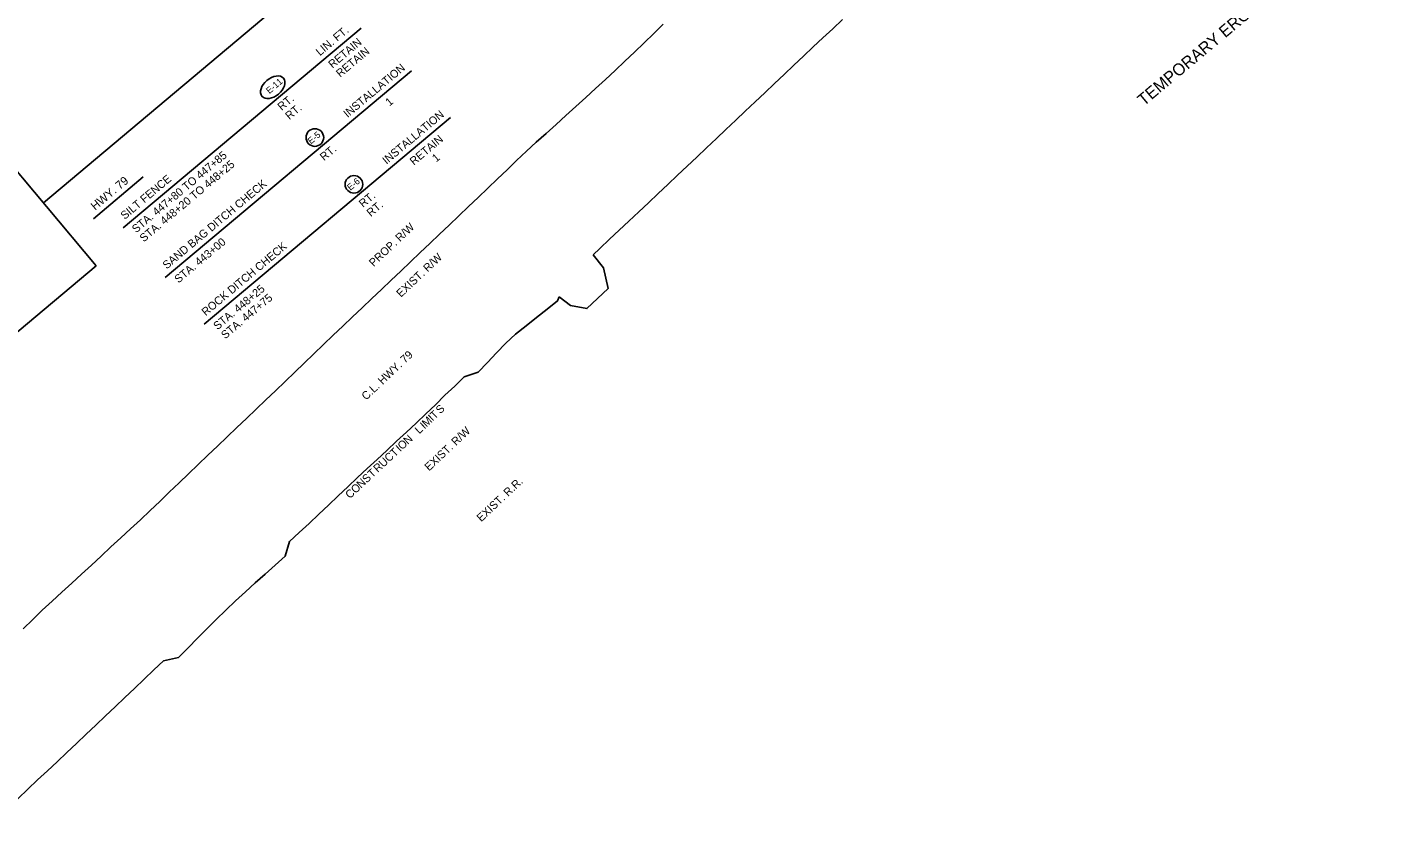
# Model space of a CAD drawing. Extents: x 1430270 to 1431940, y 1964631 to 1966264.
# Drawn here: x 1430913 to 1431940, y 1964816 to 1965408 of the extents above; entities that cross this region are included whole.
import ezdxf

# ---------------------------------------------------------------- set-up
doc = ezdxf.new("R2010")
doc.units = 0
for name, color, linetype in [('1', 7, 'Continuous'), ('44', 7, 'Continuous'), ('60', 7, 'Continuous'), ('R_Draft', 7, 'Continuous'), ('R_NO PLOT', 7, 'Continuous')]:
    doc.layers.add(name, color=color, linetype=linetype)

msp = doc.modelspace()

# ---------------------------------------------------------------- linework, layer by layer
at = {"layer": '1'}
for p, q in [((1430924.6, 1965276.1), (1431143.8, 1965460.1)), ((1430964.3, 1965228.8), (1430886.4, 1965321.6))]:
    msp.add_line(p, q, dxfattribs=at)
msp.add_lwpolyline([(1430680, 1965034.6), (1430701.8, 1965008.6), (1430964.3, 1965228.8)], dxfattribs=at)
for centre in [(1431128.1, 1965325), (1431157.4, 1965289.9)]:
    msp.add_circle(centre, 6.61, dxfattribs=at)
msp.add_ellipse((1431096.5, 1965362.7), major_axis=(8.06, 6.76), ratio=0.638788, dxfattribs=at)
at = {"layer": '44'}
for p, q in [((1430984.4, 1965257.3), (1431162.7, 1965406.9)), ((1431015.8, 1965220), (1431200.4, 1965374.9)), ((1431045.1, 1965185), (1431229.7, 1965339.9)), ((1430962.1, 1965264.1), (1430999.5, 1965295.5))]:
    msp.add_line(p, q, dxfattribs=at)
at = {"layer": 'R_NO PLOT'}
for points in [[(1430909.4, 1964956.7), (1430916.6, 1964963.7), (1430923.8, 1964970.6), (1430931.2, 1964977.4), (1430938.5, 1964984.2), (1430945.9, 1964990.9), (1430953.2, 1964997.7), (1430960.6, 1965004.4), (1430968, 1965011.2), (1430975.3, 1965018.1), (1430982.6, 1965024.8), (1430990, 1965031.6), (1430997.3, 1965038.4), (1431004.6, 1965045.3), (1431011.8, 1965052.2), (1431019, 1965059.1), (1431026.3, 1965066), (1431033.5, 1965072.9), (1431040.7, 1965079.8), (1431047.9, 1965086.8), (1431055.2, 1965093.7), (1431062.4, 1965100.6), (1431069.6, 1965107.5), (1431076.9, 1965114.4), (1431084.1, 1965121.3), (1431091.3, 1965128.2), (1431098.6, 1965135.1), (1431105.8, 1965142), (1431113, 1965149), (1431120.2, 1965155.9), (1431127.4, 1965162.9), (1431134.6, 1965169.8), (1431141.8, 1965176.7), (1431149, 1965183.6), (1431156.3, 1965190.5), (1431163.5, 1965197.4), (1431170.8, 1965204.3), (1431178.1, 1965211.1), (1431185.3, 1965218), (1431192.6, 1965224.9), (1431199.8, 1965231.8), (1431207.1, 1965238.7), (1431214.3, 1965245.6), (1431221.5, 1965252.5), (1431228.8, 1965259.4), (1431236, 1965266.3), (1431243.2, 1965273.2), (1431250.5, 1965280.1), (1431257.7, 1965287), (1431264.9, 1965294), (1431272.1, 1965300.9), (1431279.3, 1965307.8), (1431286.6, 1965314.7), (1431294, 1965321.4), (1431301.5, 1965328), (1431308.9, 1965334.8), (1431316.3, 1965341.4), (1431323.7, 1965348.3), (1431331.2, 1965354.9), (1431338.5, 1965361.7), (1431345.9, 1965368.4), (1431353.2, 1965375.3), (1431360.4, 1965382.2), (1431367.6, 1965389.1), (1431374.8, 1965396.1), (1431382.1, 1965402.9), (1431389.2, 1965409.9)], [(1431523.5, 1965413.4), (1431516.2, 1965406.5), (1431508.9, 1965399.7), (1431501.6, 1965392.9), (1431494.3, 1965386), (1431487.1, 1965379.2), (1431479.8, 1965372.3), (1431472.5, 1965365.5), (1431465.3, 1965358.6), (1431458, 1965351.7), (1431450.7, 1965344.8), (1431443.5, 1965337.9), (1431436.2, 1965331.1), (1431429, 1965324.2), (1431421.7, 1965317.3), (1431414.4, 1965310.4), (1431407.2, 1965303.6), (1431399.9, 1965296.7), (1431392.6, 1965289.8), (1431385.3, 1965283), (1431378.1, 1965276.1), (1431370.8, 1965269.3), (1431363.5, 1965262.4), (1431356.2, 1965255.6), (1431348.9, 1965248.7), (1431341.7, 1965241.8), (1431336.6, 1965237)], [(1431336.6, 1965237), (1431344.5, 1965227.2), (1431348, 1965211.8)], [(1431348, 1965211.8), (1431332, 1965196.7), (1431319.6, 1965199), (1431311.3, 1965205.5)], [(1431311.3, 1965205.5), (1431310, 1965202.5), (1431302.2, 1965196.3), (1431294.3, 1965190.1), (1431286.4, 1965183.8), (1431278.5, 1965177.6), (1431271.3, 1965170.7), (1431264.3, 1965163.5), (1431257.4, 1965156.3), (1431250.4, 1965149.1), (1431240, 1965145.5)], [(1431240, 1965145.5), (1431232.9, 1965138.6), (1431225.6, 1965131.7), (1431218.4, 1965124.7), (1431211.2, 1965117.8), (1431204, 1965110.9), (1431196.7, 1965104.1), (1431189.3, 1965097.3), (1431182, 1965090.4), (1431174.7, 1965083.6), (1431167.4, 1965076.8), (1431160.1, 1965070), (1431152.8, 1965063.1), (1431145.5, 1965056.3), (1431138.2, 1965049.4), (1431131, 1965042.6), (1431123.7, 1965035.7), (1431116.4, 1965028.9), (1431109.1, 1965022)], [(1431109.1, 1965022), (1431105.8, 1965011), (1431098.3, 1965004.3), (1431090.8, 1964997.7), (1431083.4, 1964991), (1431076, 1964984.3), (1431068.6, 1964977.5), (1431061.4, 1964970.6), (1431054.2, 1964963.6), (1431047.1, 1964956.6), (1431040.1, 1964949.5), (1431033.1, 1964942.3), (1431026, 1964935.2), (1431014.7, 1964932.7)], [(1431014.7, 1964932.7), (1431007.4, 1964925.8), (1431000.2, 1964918.9), (1430992.9, 1964912), (1430985.7, 1964905.1), (1430978.4, 1964898.2), (1430971.2, 1964891.3), (1430963.9, 1964884.5), (1430956.7, 1964877.6), (1430949.4, 1964870.7), (1430942.2, 1964863.8), (1430934.9, 1964857), (1430927.6, 1964850.1), (1430920.3, 1964843.3), (1430913, 1964836.4), (1430905.8, 1964829.5), (1430898.5, 1964822.7), (1430891.2, 1964815.8)]]:
    msp.add_lwpolyline(points, dxfattribs=at)

# ---------------------------------------------------------------- texts
at = {"layer": '1'}
for s, p in [('E-11', (1431094, 1965357.5)), ('E-5 ', (1431125.2, 1965319.8)), ('E-6 ', (1431154.7, 1965285))]:
    msp.add_text(s, height=4.8, rotation=40, dxfattribs=at).set_placement(p)
at = {"layer": '44'}
for s, height, p in [('LIN. FT.', 6, (1431131.9, 1965385.9)), ('RETAIN', 6, (1431141.3, 1965376.6)), ('RETAIN', 6, (1431147.1, 1965369.8)), ('INSTALLATION', 6, (1431152.6, 1965339.6)), ('RT.', 6, (1431103.2, 1965344.9)), ('1', 6, (1431184, 1965348.2)), ('RT.', 6, (1431109, 1965338)), ('INSTALLATION', 6, (1431181.8, 1965304.6)), ('RETAIN', 6, (1431202.3, 1965303.9)), ('STA. 447+80 TO 447+85', 6, (1430994.1, 1965253.1)), ('RT.', 6, (1431135, 1965307.2)), ('1', 6, (1431219, 1965306.2)), ('STA. 448+20 TO 448+25', 6, (1430999.9, 1965246.3)), ('HWY. 79', 6.25, (1430963.4, 1965270.1)), ('SILT FENCE      ', 6, (1430985.6, 1965263.2)), ('SAND BAG DITCH CHECK', 6, (1431017.1, 1965226)), ('RT.', 6, (1431164.2, 1965272.2)), ('RT.', 6, (1431170, 1965265.3)), ('STA. 443+00', 6, (1431025.9, 1965215.5)), ('ROCK DITCH CHECK', 6, (1431046.3, 1965190.9)), ('STA. 448+25', 6, (1431055.1, 1965180.4)), ('STA. 447+75', 6, (1431060.9, 1965173.6))]:
    msp.add_text(s, height=height, rotation=40, dxfattribs=at).set_placement(p)
at = {"layer": '60'}
msp.add_text('TEMPORARY EROSION CONTROL DETAILS', height=9, rotation=40, dxfattribs=at).set_placement((1431749.4, 1965348.2))
at = {"layer": 'R_Draft'}
for s, rotation, p in [('PROP. R/W', 43.366, (1431172.1, 1965227.8)), ('EXIST. R/W', 43.366, (1431192.6, 1965204.8)), ('C.L. HWY. 79', 43.4244, (1431166.5, 1965127.7)), ('I', 43.9648, (1431216.4, 1965112)), ('T', 43.9648, (1431217.9, 1965113.3)), ('S', 43.8895, (1431222.1, 1965117.4)), ('L', 43.0055, (1431206.3, 1965102.4)), ('I', 43.3836, (1431210.3, 1965106.1)), ('M', 43.3836, (1431211.7, 1965107.5)), ('EXIST. R/W', 43.366, (1431213.7, 1965074.6)), ('O', 43.0278, (1431193.5, 1965090.5)), ('N', 43.0278, (1431197.8, 1965094.5)), ('C', 43.0059, (1431183.6, 1965081.3)), ('T', 43.0202, (1431187.8, 1965085.1)), ('I', 43.0202, (1431192, 1965089.1)), ('T', 43.0417, (1431171, 1965069.5)), ('R', 43.0417, (1431175.3, 1965073.5)), ('U', 43.0059, (1431179.4, 1965077.3)), ('N', 43.2038, (1431162.7, 1965061.7)), ('S', 43.1533, (1431166.9, 1965065.6)), ('EXIST. R.R.', 43.3919, (1431252.8, 1965036.5)), ('C', 43.1915, (1431154.3, 1965053.8)), ('O', 43.2038, (1431158.5, 1965057.7))]:
    msp.add_text(s, height=6, rotation=rotation, dxfattribs=at).set_placement(p)

doc.saveas('drawing.dxf')
